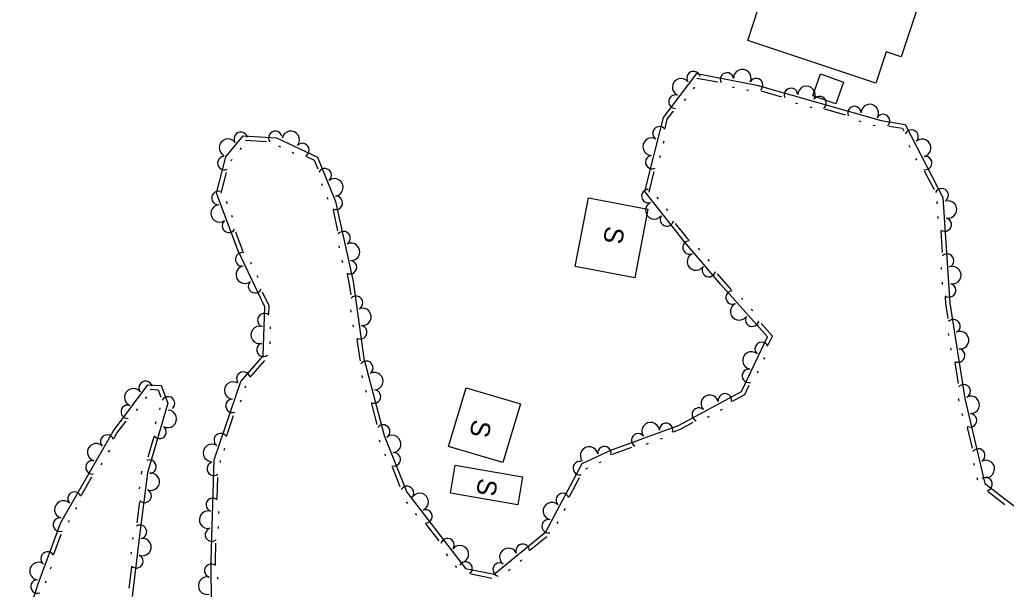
# Model space of a CAD drawing. Extents: x 2030130 to 2036320, y 723205 to 762423.
# Drawn here: x 2032715.4 to 2032905.6, y 760341.1 to 760450.9 of the extents above; entities that cross this region are included whole.
import ezdxf

# ---------------------------------------------------------------- set-up
doc = ezdxf.new("R2010")
doc.units = 0
for name, color, linetype in [('Draft_Station Tics Major', 7, 'Continuous'), ('Exist Terrain Model Ground Surface', 7, 'Continuous'), ('Old_Level_28', 7, 'Continuous')]:
    doc.layers.add(name, color=color, linetype=linetype)

msp = doc.modelspace()

# ---------------------------------------------------------------- linework, layer by layer
at = {"layer": 'Draft_Station Tics Major'}
for points in [[(2032752.41, 760328.23), (2032752.27, 760346.67), (2032752.83, 760366.05), (2032757.96, 760381.12), (2032762.33, 760386.11), (2032762.61, 760395.57), (2032757.49, 760406.34), (2032753.32, 760417.5), (2032755.12, 760424.47), (2032758.47, 760428.56), (2032764.89, 760428.14), (2032772.76, 760424.44), (2032776.27, 760415.85), (2032779.65, 760400.41), (2032781.72, 760385.55), (2032785.65, 760370.69), (2032789.98, 760359.81), (2032801.32, 760345.04), (2032806.82, 760343.97), (2032816.78, 760352.14), (2032823.84, 760365.35), (2032829.37, 760367.87), (2032842.41, 760372.68), (2032854.52, 760379.21), (2032859.52, 760389.74), (2032850.58, 760399.88), (2032843.57, 760408.12), (2032835.88, 760417.78), (2032839.47, 760432.09), (2032845.94, 760440.54), (2032857.5, 760438.31), (2032881.47, 760431.47), (2032886.1, 760430.75), (2032893.37, 760416.64), (2032894.71, 760396.27), (2032897.62, 760377.84), (2032901.47, 760361.44), (2032913.81, 760351.98)], [(2032845.94, 760439.7), (2032849.96, 760438.93)], [(2032845.26, 760437.64), (2032845.51, 760437.96)], [(2032852.71, 760437.98), (2032853.11, 760437.9)], [(2032855.53, 760437.44), (2032855.93, 760437.36)], [(2032843.52, 760435.36), (2032843.77, 760435.68)], [(2032858.33, 760437.22), (2032862.27, 760436.09)], [(2032864.92, 760434.91), (2032865.31, 760434.8)], [(2032867.68, 760434.12), (2032868.07, 760434.01)], [(2032870.55, 760433.73), (2032874.5, 760432.6)], [(2032839.8, 760430.03), (2032840.22, 760431.73), (2032841.45, 760433.33)], [(2032877.14, 760431.42), (2032877.54, 760431.31)], [(2032879.91, 760430.63), (2032880.3, 760430.52)], [(2032882.92, 760430.41), (2032885.56, 760430), (2032885.83, 760429.48)], [(2032757.89, 760425.91), (2032758.15, 760426.22)], [(2032758.87, 760427.71), (2032762.96, 760427.44)], [(2032765.27, 760426.6), (2032765.64, 760426.43)], [(2032839.5, 760427.15), (2032839.6, 760427.55)], [(2032886.78, 760426.74), (2032886.97, 760426.37)], [(2032767.87, 760425.38), (2032768.24, 760425.21)], [(2032770.64, 760424.53), (2032772.12, 760423.84), (2032772.81, 760422.15)], [(2032838.8, 760424.37), (2032838.9, 760424.76)], [(2032888.1, 760424.18), (2032888.29, 760423.82)], [(2032756.08, 760423.69), (2032756.34, 760424)], [(2032754.17, 760417.51), (2032755.2, 760421.48)], [(2032836.71, 760417.7), (2032837.7, 760421.68)], [(2032889.78, 760421.82), (2032891.66, 760418.18)], [(2032773.52, 760419.33), (2032773.67, 760418.96)], [(2032774.6, 760416.68), (2032774.76, 760416.3)], [(2032838.55, 760416.4), (2032838.3, 760416.72)], [(2032755.4, 760415.45), (2032755.25, 760415.84)], [(2032892.19, 760415.84), (2032892.22, 760415.43)], [(2032756.4, 760412.76), (2032756.26, 760413.15)], [(2032775.78, 760414.23), (2032776.66, 760410.23)], [(2032840.34, 760414.15), (2032840.08, 760414.47)], [(2032892.38, 760412.98), (2032892.41, 760412.57)], [(2032844.35, 760408.47), (2032844.21, 760408.64), (2032841.81, 760411.65)], [(2032758.47, 760406.17), (2032758.24, 760406.66), (2032757.02, 760409.93)], [(2032892.98, 760410.14), (2032893.25, 760406.05)], [(2032776.88, 760407.34), (2032776.96, 760406.94)], [(2032846.52, 760406.55), (2032846.26, 760406.86)], [(2032760.08, 760403.76), (2032759.9, 760404.13)], [(2032777.49, 760404.53), (2032777.58, 760404.13)], [(2032848.38, 760404.36), (2032848.12, 760404.67)], [(2032761.31, 760401.16), (2032761.13, 760401.53)], [(2032778.51, 760401.82), (2032778.84, 760400.27), (2032779.18, 760397.84)], [(2032852.61, 760398.82), (2032851.2, 760400.41), (2032849.93, 760401.91)], [(2032893.03, 760403.15), (2032893.06, 760402.75)], [(2032893.22, 760400.29), (2032893.24, 760399.88)], [(2032763.39, 760394.18), (2032763.43, 760395.74), (2032762.17, 760398.39)], [(2032854.81, 760396.94), (2032854.54, 760397.25)], [(2032893.81, 760397.45), (2032893.9, 760396.18), (2032894.35, 760393.32)], [(2032779.17, 760394.94), (2032779.23, 760394.53)], [(2032856.71, 760394.79), (2032856.44, 760395.09)], [(2032779.57, 760392.09), (2032779.63, 760391.69)], [(2032859.69, 760388.19), (2032860.5, 760389.88), (2032858.31, 760392.36)], [(2032763.71, 760391.3), (2032763.72, 760391.71)], [(2032894.39, 760390.42), (2032894.45, 760390.01)], [(2032763.63, 760388.43), (2032763.64, 760388.84)], [(2032780.37, 760389.31), (2032780.92, 760385.39), (2032780.98, 760385.15)], [(2032894.84, 760387.58), (2032894.9, 760387.17)], [(2032759.91, 760382.1), (2032762.61, 760385.18)], [(2032858.83, 760385.42), (2032859.01, 760385.79)], [(2032895.69, 760384.81), (2032896.33, 760380.76)], [(2032781.32, 760382.27), (2032781.42, 760381.88)], [(2032857.6, 760382.83), (2032857.78, 760383.2)], [(2032715.36, 760331.21), (2032718.94, 760342.11), (2032723.28, 760353.95), (2032733.42, 760371.62), (2032740.05, 760380.47), (2032742.62, 760380.36), (2032743.93, 760376.96), (2032740.02, 760363.49), (2032738.52, 760351.95), (2032737.05, 760339.66)], [(2032852.81, 760377.36), (2032855.15, 760378.62), (2032856, 760380.41)], [(2032740.53, 760379.63), (2032742.05, 760379.56), (2032742.59, 760378.15)], [(2032758.85, 760379.91), (2032758.98, 760380.3)], [(2032782.05, 760379.5), (2032782.16, 760379.1)], [(2032739.62, 760377.85), (2032739.87, 760378.18)], [(2032757.93, 760377.2), (2032758.06, 760377.58)], [(2032783.18, 760376.83), (2032784.23, 760372.86)], [(2032896.37, 760377.86), (2032896.41, 760377.6), (2032896.46, 760377.36)], [(2032737.9, 760375.55), (2032738.15, 760375.88)], [(2032742.4, 760376.08), (2032742.28, 760375.69)], [(2032850.48, 760375.64), (2032850.84, 760375.83)], [(2032897.03, 760374.97), (2032897.12, 760374.57)], [(2032733.57, 760370.22), (2032734.11, 760371.17), (2032735.85, 760373.5)], [(2032741.59, 760373.33), (2032741.48, 760372.93)], [(2032755.29, 760370.73), (2032756.61, 760374.61)], [(2032841.44, 760371.44), (2032842.75, 760371.93), (2032845.23, 760373.27)], [(2032847.95, 760374.27), (2032848.31, 760374.47)], [(2032898.08, 760372.27), (2032899.02, 760368.28)], [(2032741.19, 760370.45), (2032740.04, 760366.52)], [(2032784.66, 760369.86), (2032784.81, 760369.48)], [(2032836.19, 760369.07), (2032836.58, 760369.22)], [(2032838.89, 760370.07), (2032839.27, 760370.21)], [(2032732.49, 760367.53), (2032732.7, 760367.88)], [(2032754.76, 760367.88), (2032754.89, 760368.27)], [(2032785.72, 760367.19), (2032785.87, 760366.81)], [(2032829.57, 760367.06), (2032829.68, 760367.11), (2032833.36, 760368.47)], [(2032731.06, 760365.04), (2032731.27, 760365.39)], [(2032754.05, 760365.49), (2032754.06, 760365.91)], [(2032827.13, 760365.5), (2032827.5, 760365.67)], [(2032899.28, 760365.39), (2032899.38, 760364.99)], [(2032738.84, 760363.86), (2032738.81, 760363.74), (2032738.75, 760363.28)], [(2032787.16, 760364.67), (2032788.67, 760360.86)], [(2032824.52, 760364.3), (2032824.89, 760364.47)], [(2032727.24, 760359.19), (2032729.28, 760362.75)], [(2032753.44, 760358.54), (2032753.56, 760362.64)], [(2032821.36, 760358.97), (2032823.3, 760362.59)], [(2032899.94, 760362.59), (2032900.03, 760362.19)], [(2032738.43, 760360.84), (2032738.38, 760360.44)], [(2032902.08, 760359.94), (2032905.34, 760357.44)], [(2032738.47, 760357.94), (2032737.94, 760353.88)], [(2032789.86, 760357.94), (2032790.11, 760357.62)], [(2032726.16, 760356.5), (2032726.37, 760356.85)], [(2032753.76, 760355.66), (2032753.78, 760356.07)], [(2032791.61, 760355.66), (2032791.86, 760355.34)], [(2032820.37, 760356.25), (2032820.57, 760356.61)], [(2032724.73, 760354.01), (2032724.94, 760354.37)], [(2032819.02, 760353.72), (2032819.21, 760354.08)], [(2032753.68, 760352.78), (2032753.69, 760353.19)], [(2032793.68, 760353.64), (2032796.18, 760350.39)], [(2032721.92, 760347.85), (2032723.33, 760351.7)], [(2032737.17, 760351.07), (2032737.13, 760350.66)], [(2032753.1, 760345.86), (2032753.09, 760346.66), (2032753.19, 760349.93)], [(2032813.8, 760348.64), (2032816.97, 760351.24)], [(2032736.83, 760348.22), (2032736.79, 760347.81)], [(2032797.61, 760347.86), (2032797.86, 760347.53)], [(2032811.84, 760346.5), (2032812.16, 760346.76)], [(2032721.32, 760345.01), (2032721.46, 760345.4)], [(2032736.9, 760345.32), (2032736.42, 760341.25)], [(2032799.35, 760345.58), (2032799.6, 760345.26)], [(2032809.62, 760344.68), (2032809.94, 760344.94)], [(2032720.32, 760342.32), (2032720.47, 760342.7)], [(2032753.53, 760342.99), (2032753.53, 760343.4)], [(2032802.38, 760344), (2032806.41, 760343.22)]]:
    msp.add_lwpolyline(points, dxfattribs=at)
for centre, radius, start, end in [((2032854.7, 760439.68), 1.69, 335.0585, 183.131), ((2032842.89, 760437.91), 1.69, 38.5196, 246.5921), ((2032845.28, 760439.69), 1.3, 13.3243, 214.1209), ((2032851.73, 760439.42), 1.3, 7.5297, 208.3262), ((2032857.37, 760438.34), 1.3, 309.8632, 150.6598), ((2032864.07, 760436.43), 1.3, 2.5022, 203.2988), ((2032867.06, 760436.43), 1.69, 330.031, 178.1035), ((2032841.79, 760435.13), 1.3, 70.9908, 271.7874), ((2032869.59, 760434.86), 1.3, 304.8358, 145.6323), ((2032876.3, 760432.94), 1.3, 2.5022, 203.2988), ((2032879.28, 760432.94), 1.69, 330.031, 178.1035), ((2032881.83, 760431.41), 1.3, 311.9582, 152.7548), ((2032838.7, 760429.04), 1.3, 36.7021, 237.4987), ((2032755.53, 760426.25), 1.69, 36.6806, 244.7531), ((2032757.98, 760427.96), 1.3, 11.4853, 212.2819), ((2032764.65, 760428.15), 1.3, 14.7059, 215.5025), ((2032767.62, 760427.76), 1.69, 320.7937, 168.8662), ((2032837.21, 760426.45), 1.69, 61.8974, 269.9699), ((2032887.31, 760428.39), 1.3, 315.7084, 156.505), ((2032889.36, 760426.22), 1.69, 283.2372, 131.3097), ((2032769.87, 760425.8), 1.3, 295.5984, 136.395), ((2032754.82, 760423.27), 1.3, 93.911, 294.7076), ((2032837.31, 760423.47), 1.3, 94.3686, 295.1652), ((2032889.95, 760423.29), 1.3, 258.0419, 98.8385), ((2032774.19, 760420.94), 1.3, 310.6631, 151.4597), ((2032776.03, 760418.59), 1.69, 278.1919, 126.2644), ((2032893.14, 760417.09), 1.3, 315.7084, 156.505), ((2032753.67, 760416.56), 1.3, 71.2516, 272.0481), ((2032776.32, 760415.61), 1.3, 243.1302, 83.9267), ((2032836.57, 760416.91), 1.3, 89.3076, 290.1042), ((2032753.91, 760413.58), 1.69, 96.4468, 304.5193), ((2032837.71, 760414.16), 1.69, 114.5029, 322.5754), ((2032894.35, 760414.34), 1.69, 259.7308, 107.8033), ((2032840.14, 760412.42), 1.3, 146.9741, 347.7706), ((2032755.68, 760411.18), 1.3, 128.918, 329.7146), ((2032893.72, 760411.42), 1.3, 234.5355, 75.3321), ((2032777.81, 760408.8), 1.3, 300.7966, 141.5932), ((2032779.23, 760406.17), 1.69, 268.3255, 116.3979), ((2032844.52, 760407), 1.3, 91.1357, 291.9322), ((2032758.26, 760404.71), 1.3, 76.1866, 276.9832), ((2032845.76, 760404.28), 1.69, 116.3309, 324.4034), ((2032894.18, 760404.46), 1.3, 292.202, 132.9986), ((2032758.75, 760401.76), 1.69, 101.3819, 309.4544), ((2032779.04, 760403.19), 1.3, 243.1302, 83.9267), ((2032848.24, 760402.63), 1.3, 148.8021, 349.5987), ((2032895.18, 760401.65), 1.69, 259.7308, 107.8033), ((2032760.73, 760399.52), 1.3, 133.8531, 334.6496), ((2032894.55, 760398.73), 1.3, 234.5355, 75.3321), ((2032780.22, 760396.33), 1.3, 296.3706, 137.1672), ((2032852.81, 760397.35), 1.3, 92.1941, 292.9907), ((2032854.09, 760394.66), 1.69, 117.3894, 325.4619), ((2032762.53, 760392.98), 1.3, 49.0737, 249.8703), ((2032781.43, 760393.6), 1.69, 263.8994, 111.9719), ((2032856.6, 760393.05), 1.3, 149.8606, 350.6572), ((2032761.63, 760390.13), 1.69, 74.269, 282.3415), ((2032781.01, 760390.64), 1.3, 238.7042, 79.5007), ((2032895.41, 760391.82), 1.3, 297.3777, 138.1743), ((2032896.67, 760389.11), 1.69, 264.9065, 112.979), ((2032762.36, 760387.24), 1.3, 106.7402, 307.5368), ((2032858.43, 760387.43), 1.3, 25.3395, 226.136), ((2032856.45, 760385.19), 1.69, 50.5347, 258.6072), ((2032896.31, 760386.15), 1.3, 239.7113, 80.5078), ((2032782.19, 760383.78), 1.3, 303.2394, 144.0359), ((2032758.48, 760381.71), 1.3, 9.5959, 210.3925), ((2032783.72, 760381.21), 1.69, 270.7682, 118.8406), ((2032855.96, 760382.24), 1.3, 83.0059, 283.8025), ((2032739.62, 760379.9), 1.3, 13.9573, 214.7538), ((2032756.51, 760379.41), 1.69, 57.176, 265.2485), ((2032897.39, 760379.26), 1.3, 297.3777, 138.1743), ((2032737.24, 760378.09), 1.69, 39.1525, 247.225), ((2032783.66, 760378.23), 1.3, 245.5729, 86.3695), ((2032848.42, 760376.85), 1.69, 14.3295, 222.402), ((2032851.34, 760377.5), 1.3, 349.1342, 189.9308), ((2032736.18, 760375.3), 1.3, 71.6237, 272.4203), ((2032743.95, 760376.92), 1.3, 309.6347, 150.4312), ((2032756.37, 760376.43), 1.3, 89.6472, 290.4438), ((2032898.74, 760376.64), 1.69, 269.2083, 117.2808), ((2032743.91, 760373.93), 1.69, 239.7529, 87.8254), ((2032846.29, 760374.77), 1.3, 46.8007, 247.5973), ((2032898.6, 760373.65), 1.3, 244.013, 84.8096), ((2032785.44, 760371.49), 1.3, 303.2394, 144.0359), ((2032837.02, 760371.57), 1.69, 6.1853, 214.2578), ((2032840, 760371.79), 1.3, 340.99, 181.7866), ((2032732.24, 760369.56), 1.3, 20.9114, 221.708), ((2032742.32, 760371.41), 1.3, 214.5576, 55.3542), ((2032754.12, 760369.83), 1.3, 31.9807, 232.7773), ((2032834.61, 760369.8), 1.3, 38.6565, 239.453), ((2032730.1, 760367.48), 1.69, 46.1067, 254.1792), ((2032752.42, 760367.37), 1.69, 57.176, 265.2485), ((2032787.17, 760369.09), 1.69, 277.6377, 125.7102), ((2032787.47, 760366.12), 1.3, 252.4424, 93.239), ((2032825.16, 760366.85), 1.69, 10.5337, 218.6062), ((2032828.11, 760367.3), 1.3, 345.3385, 186.135), ((2032900.2, 760366.87), 1.3, 301.6795, 142.476), ((2032729.38, 760364.58), 1.3, 78.5779, 279.3745), ((2032740.37, 760364.71), 1.3, 272.2241, 113.0206), ((2032752.78, 760364.3), 1.3, 106.7744, 307.5709), ((2032823.35, 760364.42), 1.3, 80.3045, 281.1011), ((2032901.65, 760364.26), 1.69, 269.2083, 117.2808), ((2032740.62, 760361.8), 1.69, 248.5693, 96.6417), ((2032901.61, 760361.34), 1.3, 283.2757, 124.0722), ((2032725.91, 760358.54), 1.3, 20.9114, 221.708), ((2032739.44, 760359.06), 1.3, 223.374, 64.1706), ((2032790.04, 760359.64), 1.3, 310.1089, 150.9055), ((2032792.49, 760357.89), 1.69, 293.4971, 141.5696), ((2032820.06, 760358.27), 1.3, 22.638, 223.4346), ((2032723.77, 760356.45), 1.69, 46.1067, 254.1792), ((2032752.58, 760357.33), 1.3, 49.1079, 249.9045), ((2032817.98, 760356.13), 1.69, 47.8333, 255.9058), ((2032751.68, 760354.48), 1.69, 74.3032, 282.3756), ((2032793.58, 760355.11), 1.3, 268.3019, 109.0984), ((2032723.12, 760353.52), 1.3, 88.2918, 289.0883), ((2032817.35, 760353.21), 1.3, 80.3045, 281.1011), ((2032738.54, 760352.14), 1.3, 281.0405, 121.837), ((2032752.42, 760351.59), 1.3, 106.7744, 307.5709), ((2032739.02, 760349.2), 1.69, 249.1557, 97.2282), ((2032797.83, 760349.58), 1.3, 325.9683, 166.7649), ((2032720.72, 760346.98), 1.3, 30.6253, 231.4219), ((2032800.23, 760347.81), 1.69, 293.4971, 141.5696), ((2032809.59, 760347.3), 1.69, 25.3158, 233.3883), ((2032812.33, 760348.49), 1.3, 0.1205, 200.9171), ((2032718.97, 760344.57), 1.69, 55.8206, 263.8931), ((2032737.86, 760346.44), 1.3, 223.9604, 64.757), ((2032801.33, 760345.04), 1.3, 309.8256, 150.6222), ((2032807.89, 760344.85), 1.3, 57.787, 258.5836), ((2032752.29, 760344.62), 1.3, 51.2069, 252.0034), ((2032718.76, 760341.58), 1.3, 90.25, 291.0465), ((2032751.49, 760341.74), 1.69, 76.4022, 284.4746)]:
    msp.add_arc(centre, radius, start, end, dxfattribs=at)
at = {"layer": 'Exist Terrain Model Ground Surface'}
for points in [[(2032856, 760453.62), (2032867.86, 760489.25), (2032897.22, 760479.47), (2032885.35, 760443.79), (2032882.42, 760444.77), (2032880.41, 760438.71), (2032855.74, 760446.91), (2032857.78, 760453.03)], [(2032869.78, 760440.5), (2032874.23, 760438.91), (2032872.72, 760434.69), (2032868.27, 760436.27)], [(2032822.49, 760403.32), (2032825.02, 760416.57), (2032836.49, 760414.37), (2032833.95, 760401.13)], [(2032811.89, 760376.83), (2032808.51, 760365.49), (2032798.04, 760368.61), (2032801.42, 760379.95)], [(2032799.3, 760364.97), (2032812.33, 760362.74), (2032811.41, 760357.36), (2032798.39, 760359.59)]]:
    msp.add_lwpolyline(points, close=True, dxfattribs=at)

# ---------------------------------------------------------------- texts
at = {"layer": 'Old_Level_28'}
for rotation, p in [(259.1727, (2032828.42, 760411.31)), (259.289, (2032802.7, 760373.97)), (260.2643, (2032803.91, 760362.65))]:
    msp.add_text('S', height=3.69, rotation=rotation, dxfattribs=at).set_placement(p)

doc.saveas('drawing.dxf')
